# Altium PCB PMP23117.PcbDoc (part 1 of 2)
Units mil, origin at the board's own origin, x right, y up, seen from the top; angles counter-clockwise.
Board outline 3300 x 2800 mil, 6 copper layers (Top Layer, GND Layer 1, Signal Layer 1, GND Layer 2, Signal Layer3, Bottom Layer), stack 62.8 mil thick; 125 components, 38 nets, 250 pads, 683 vias.
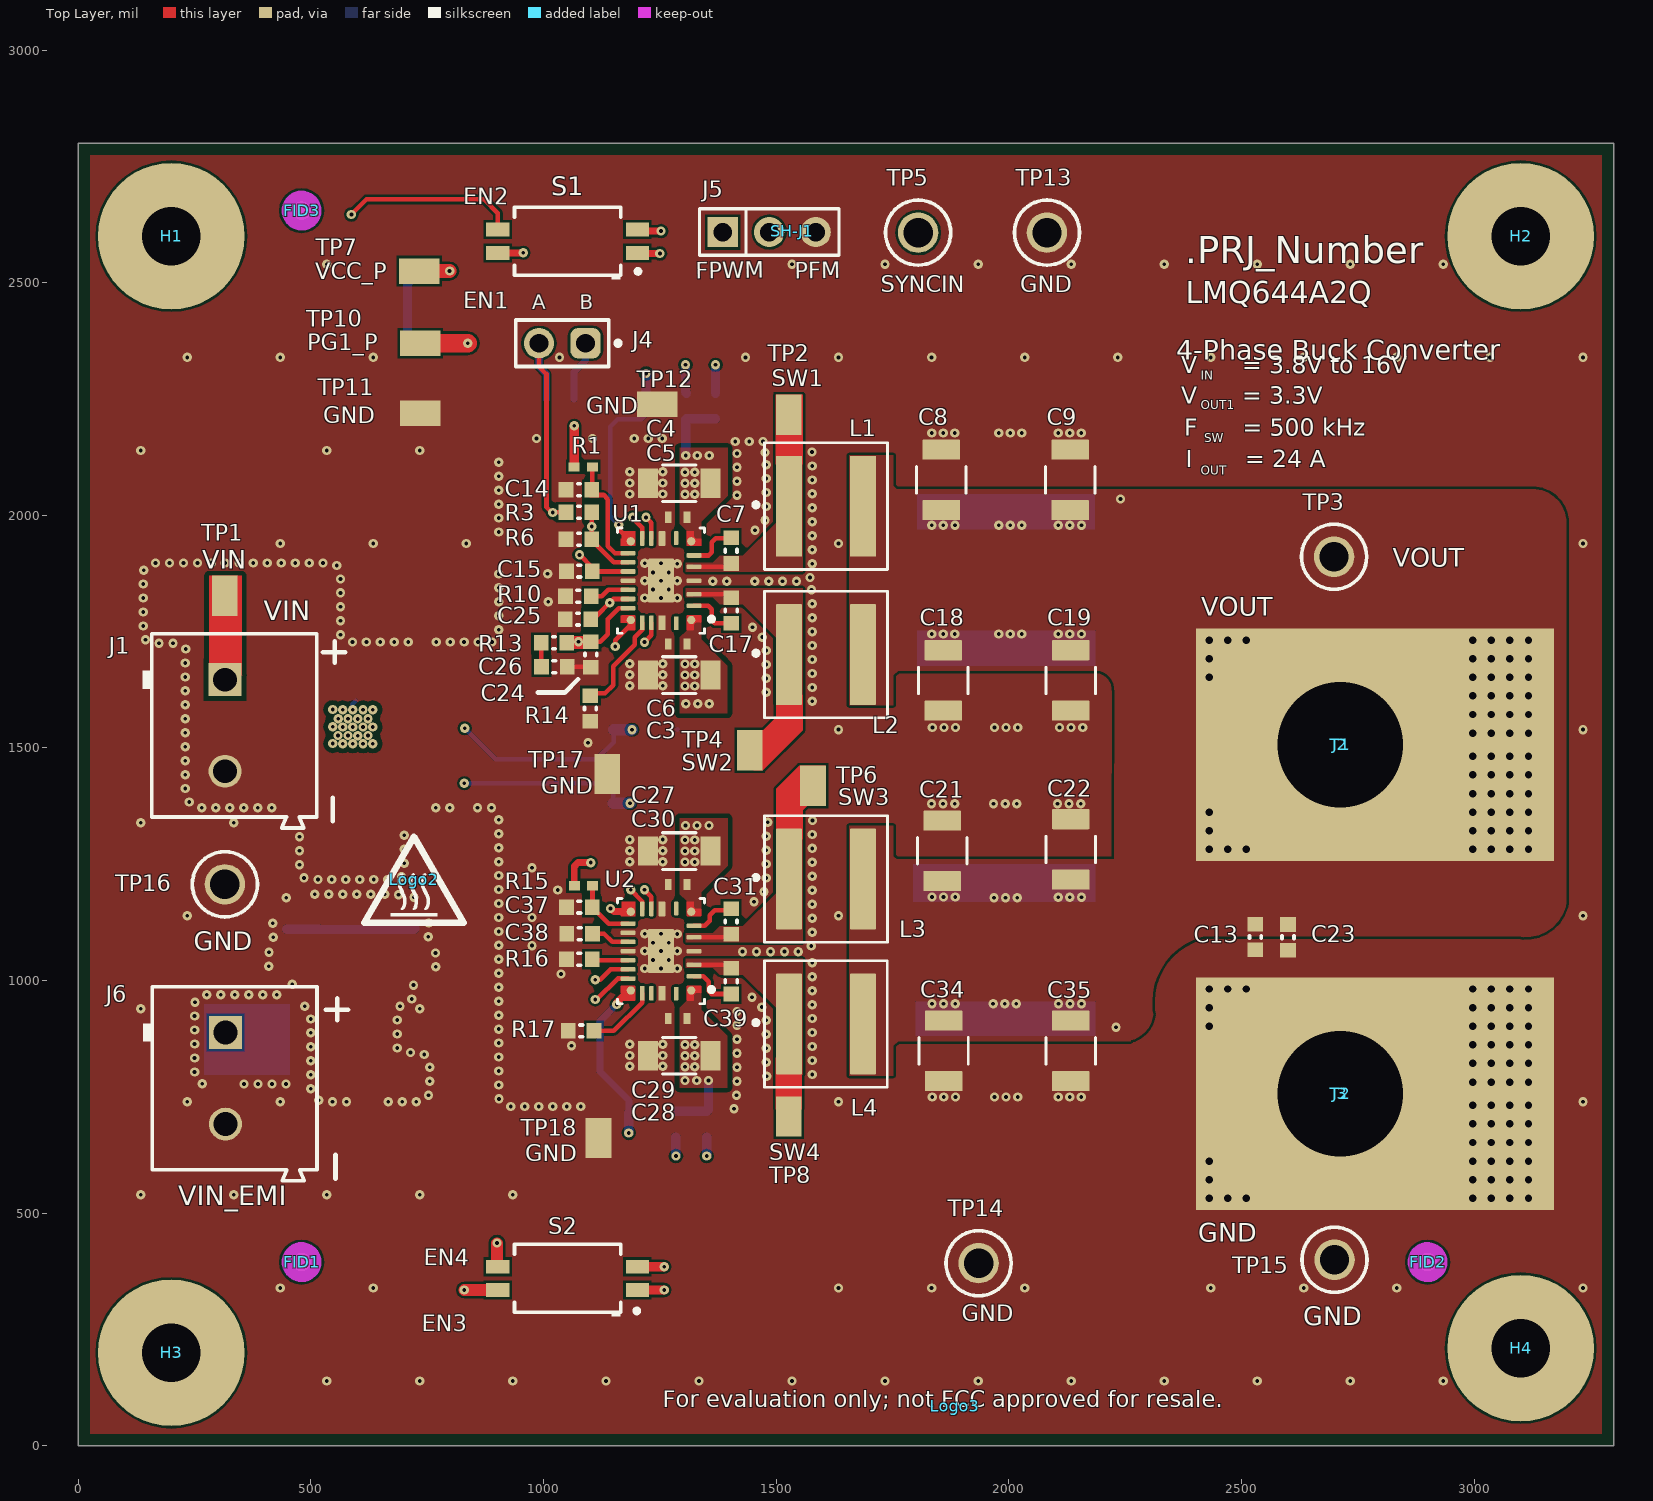
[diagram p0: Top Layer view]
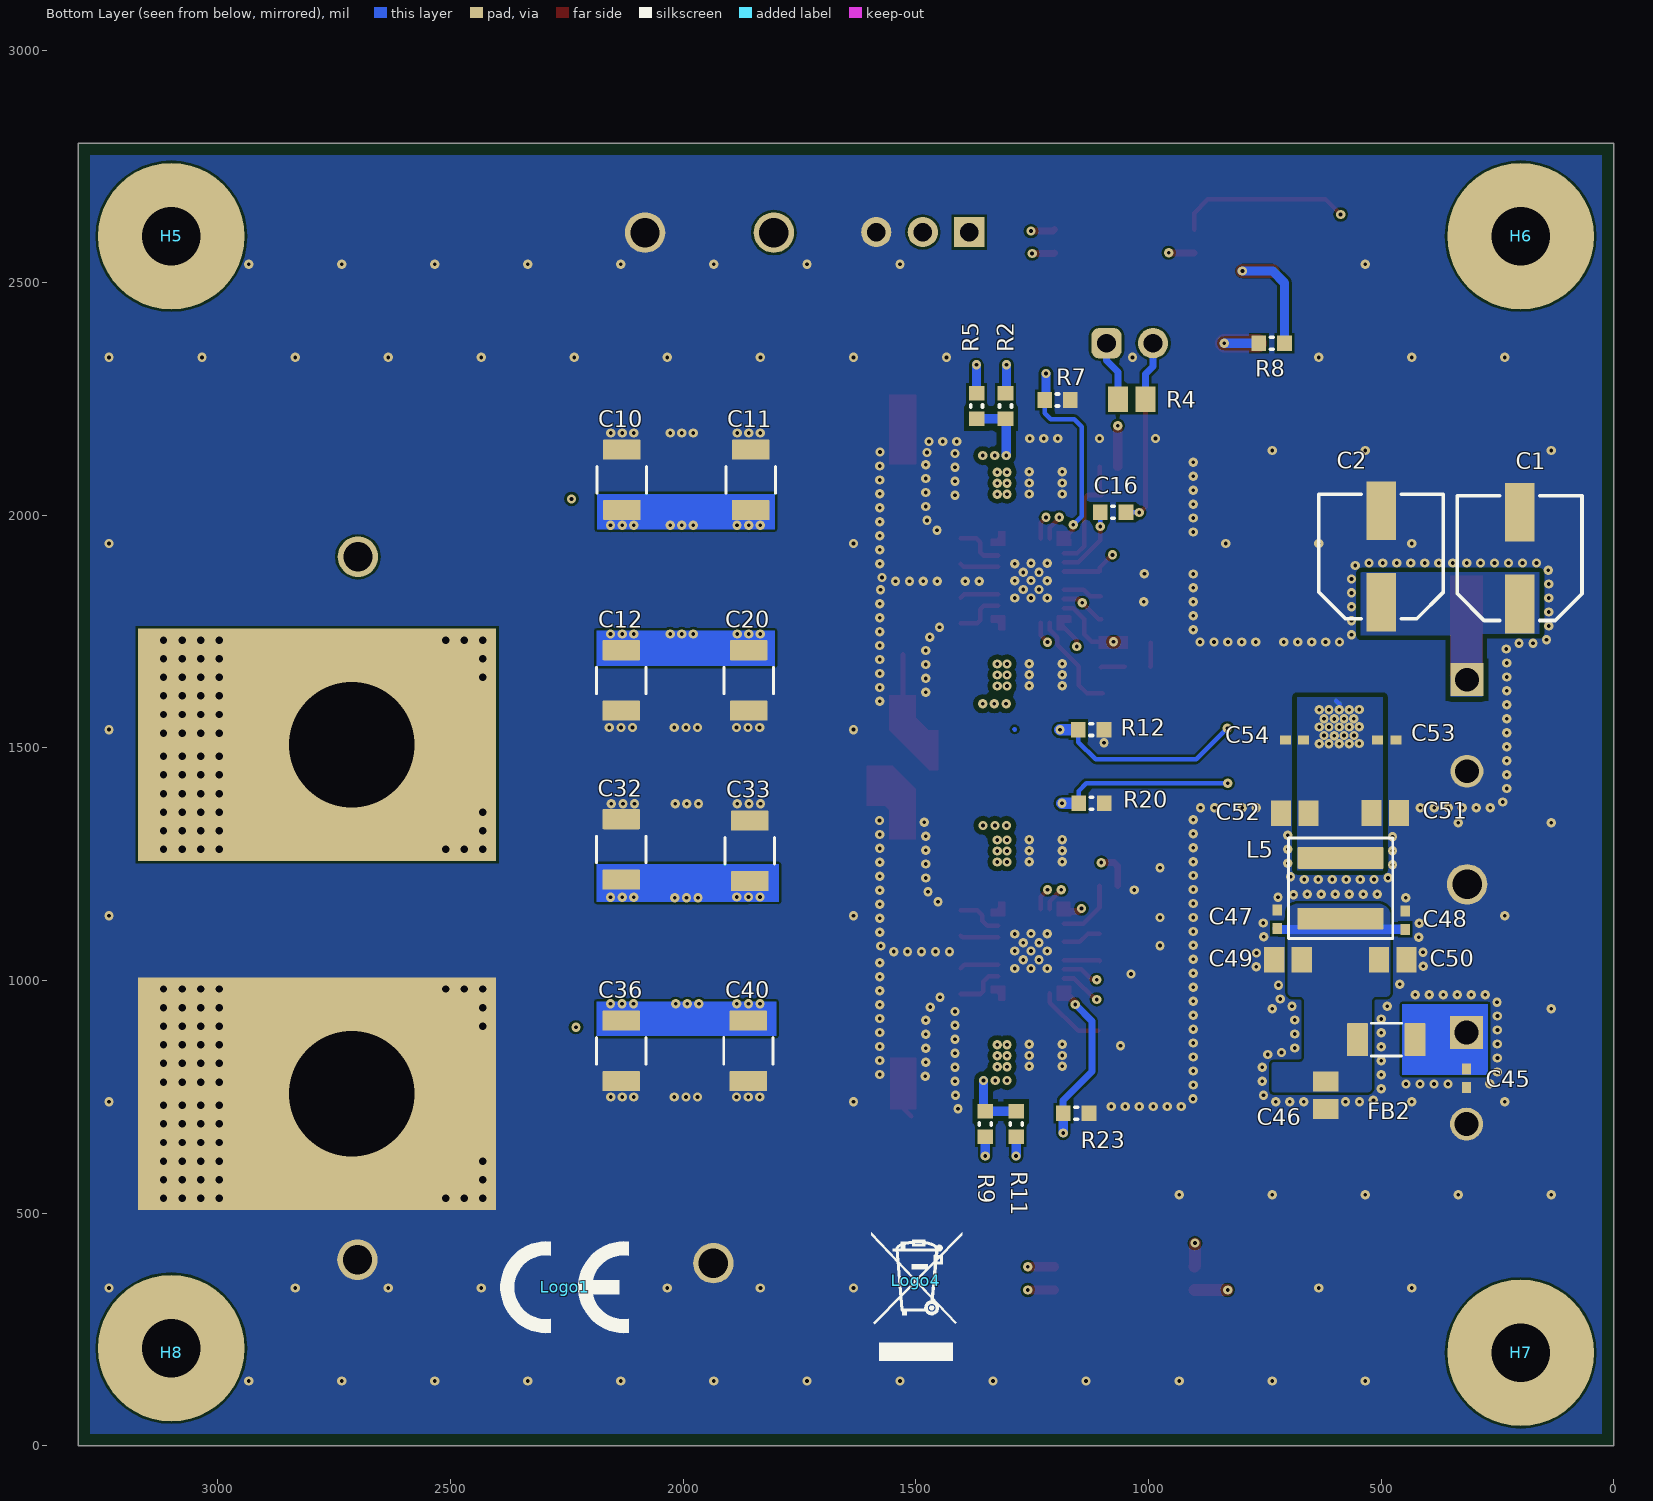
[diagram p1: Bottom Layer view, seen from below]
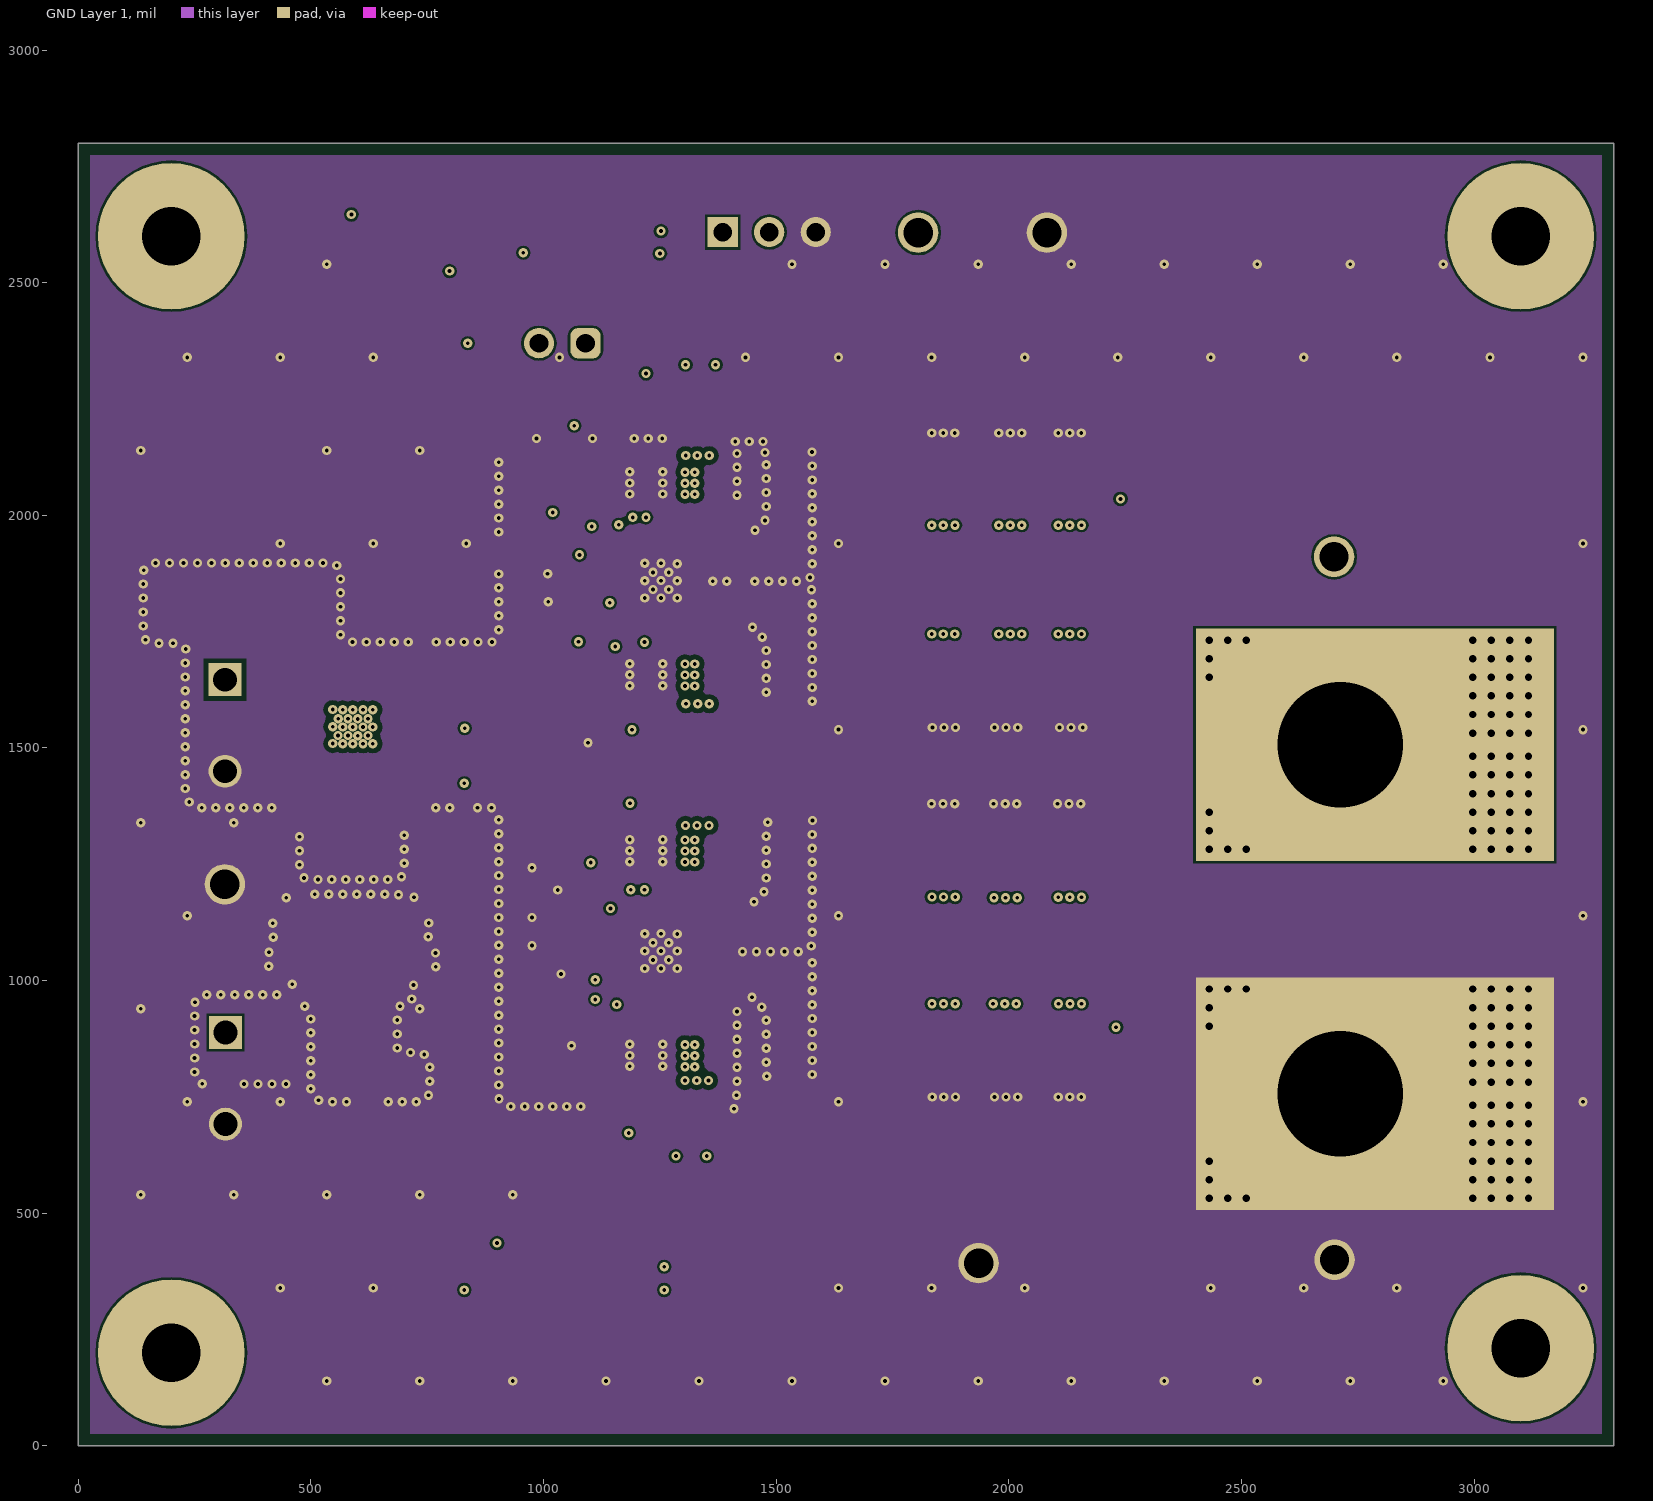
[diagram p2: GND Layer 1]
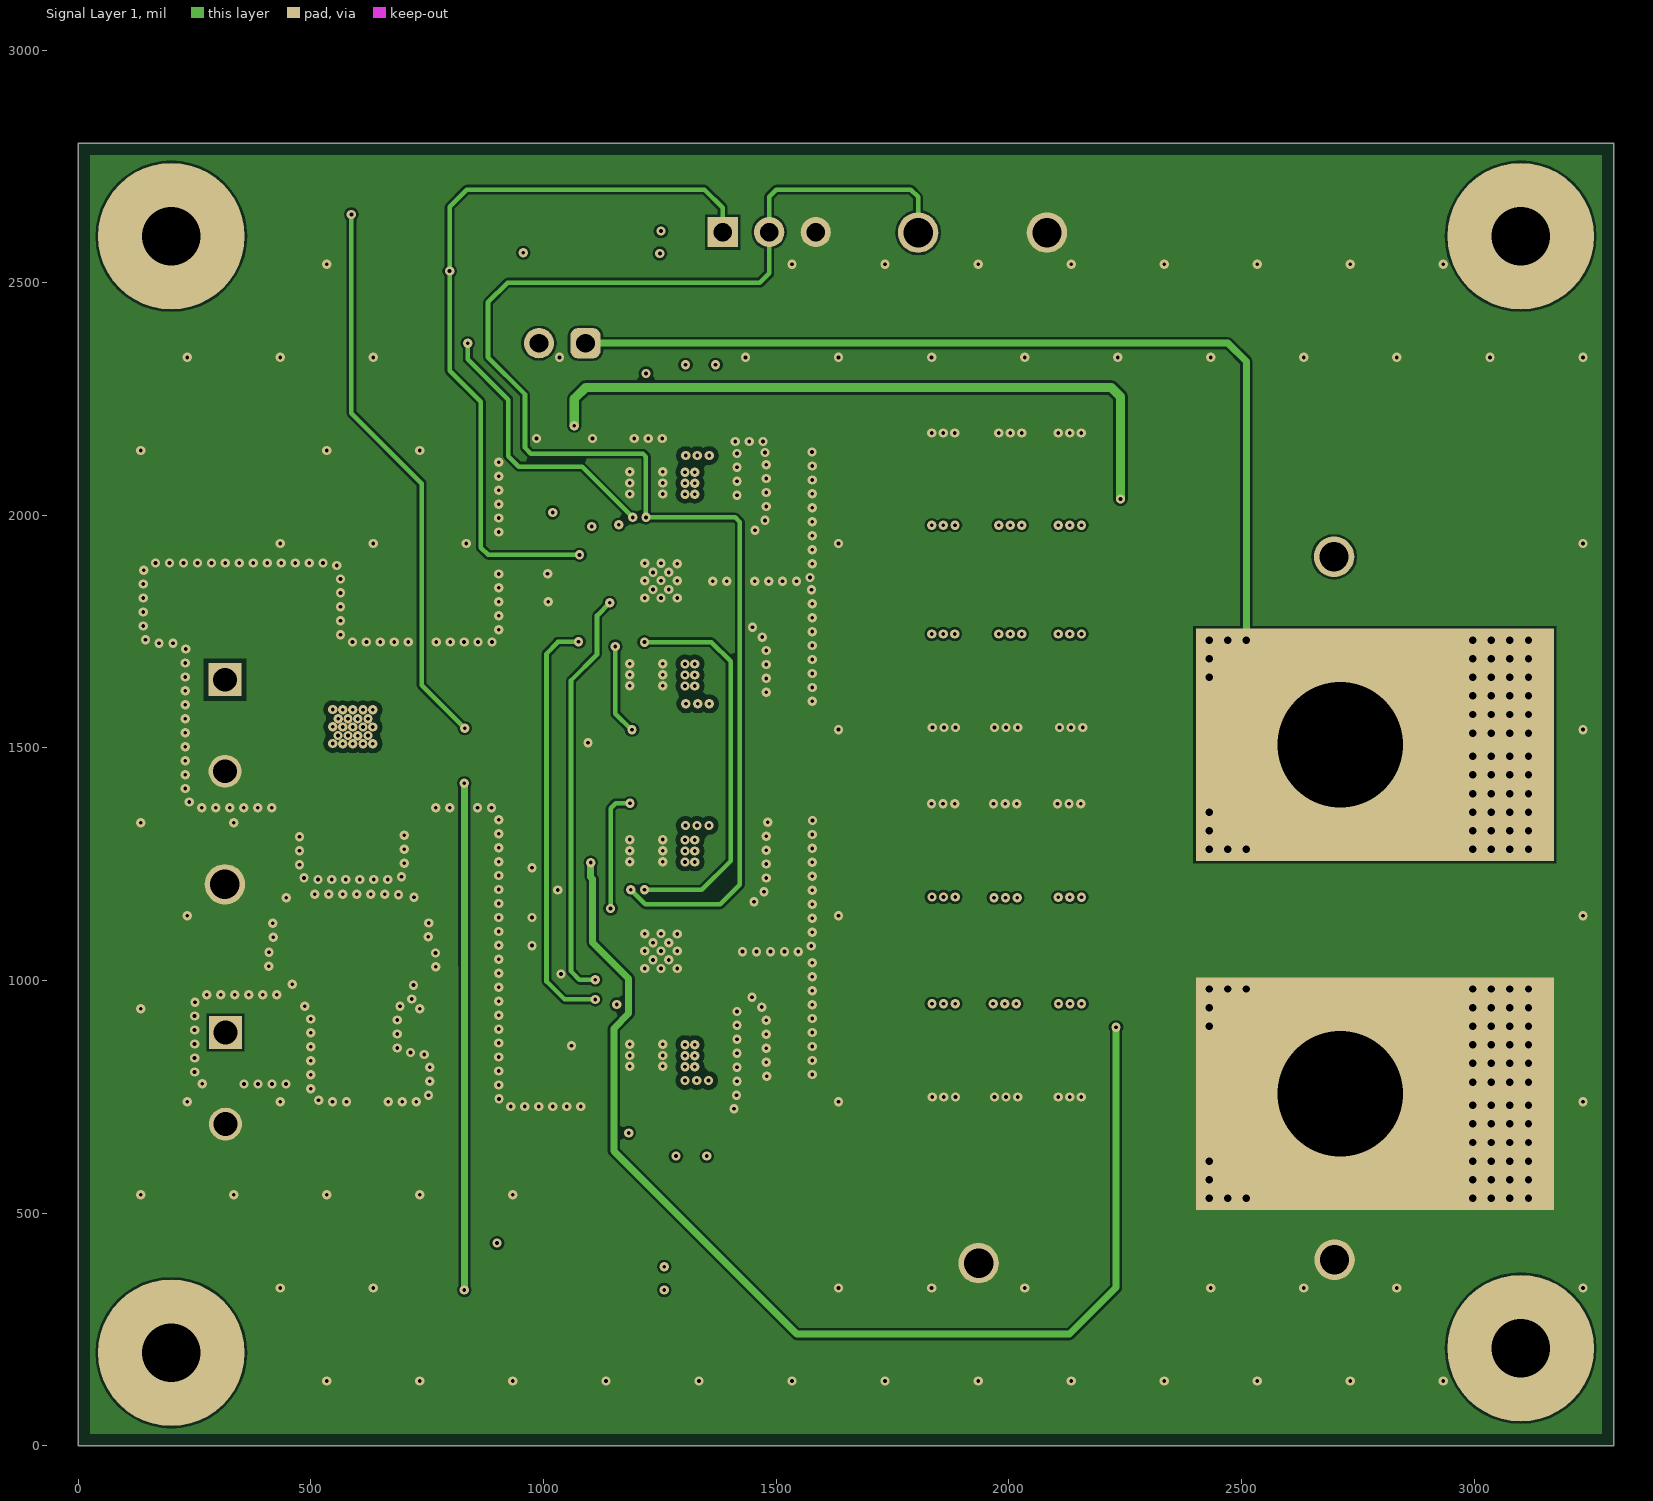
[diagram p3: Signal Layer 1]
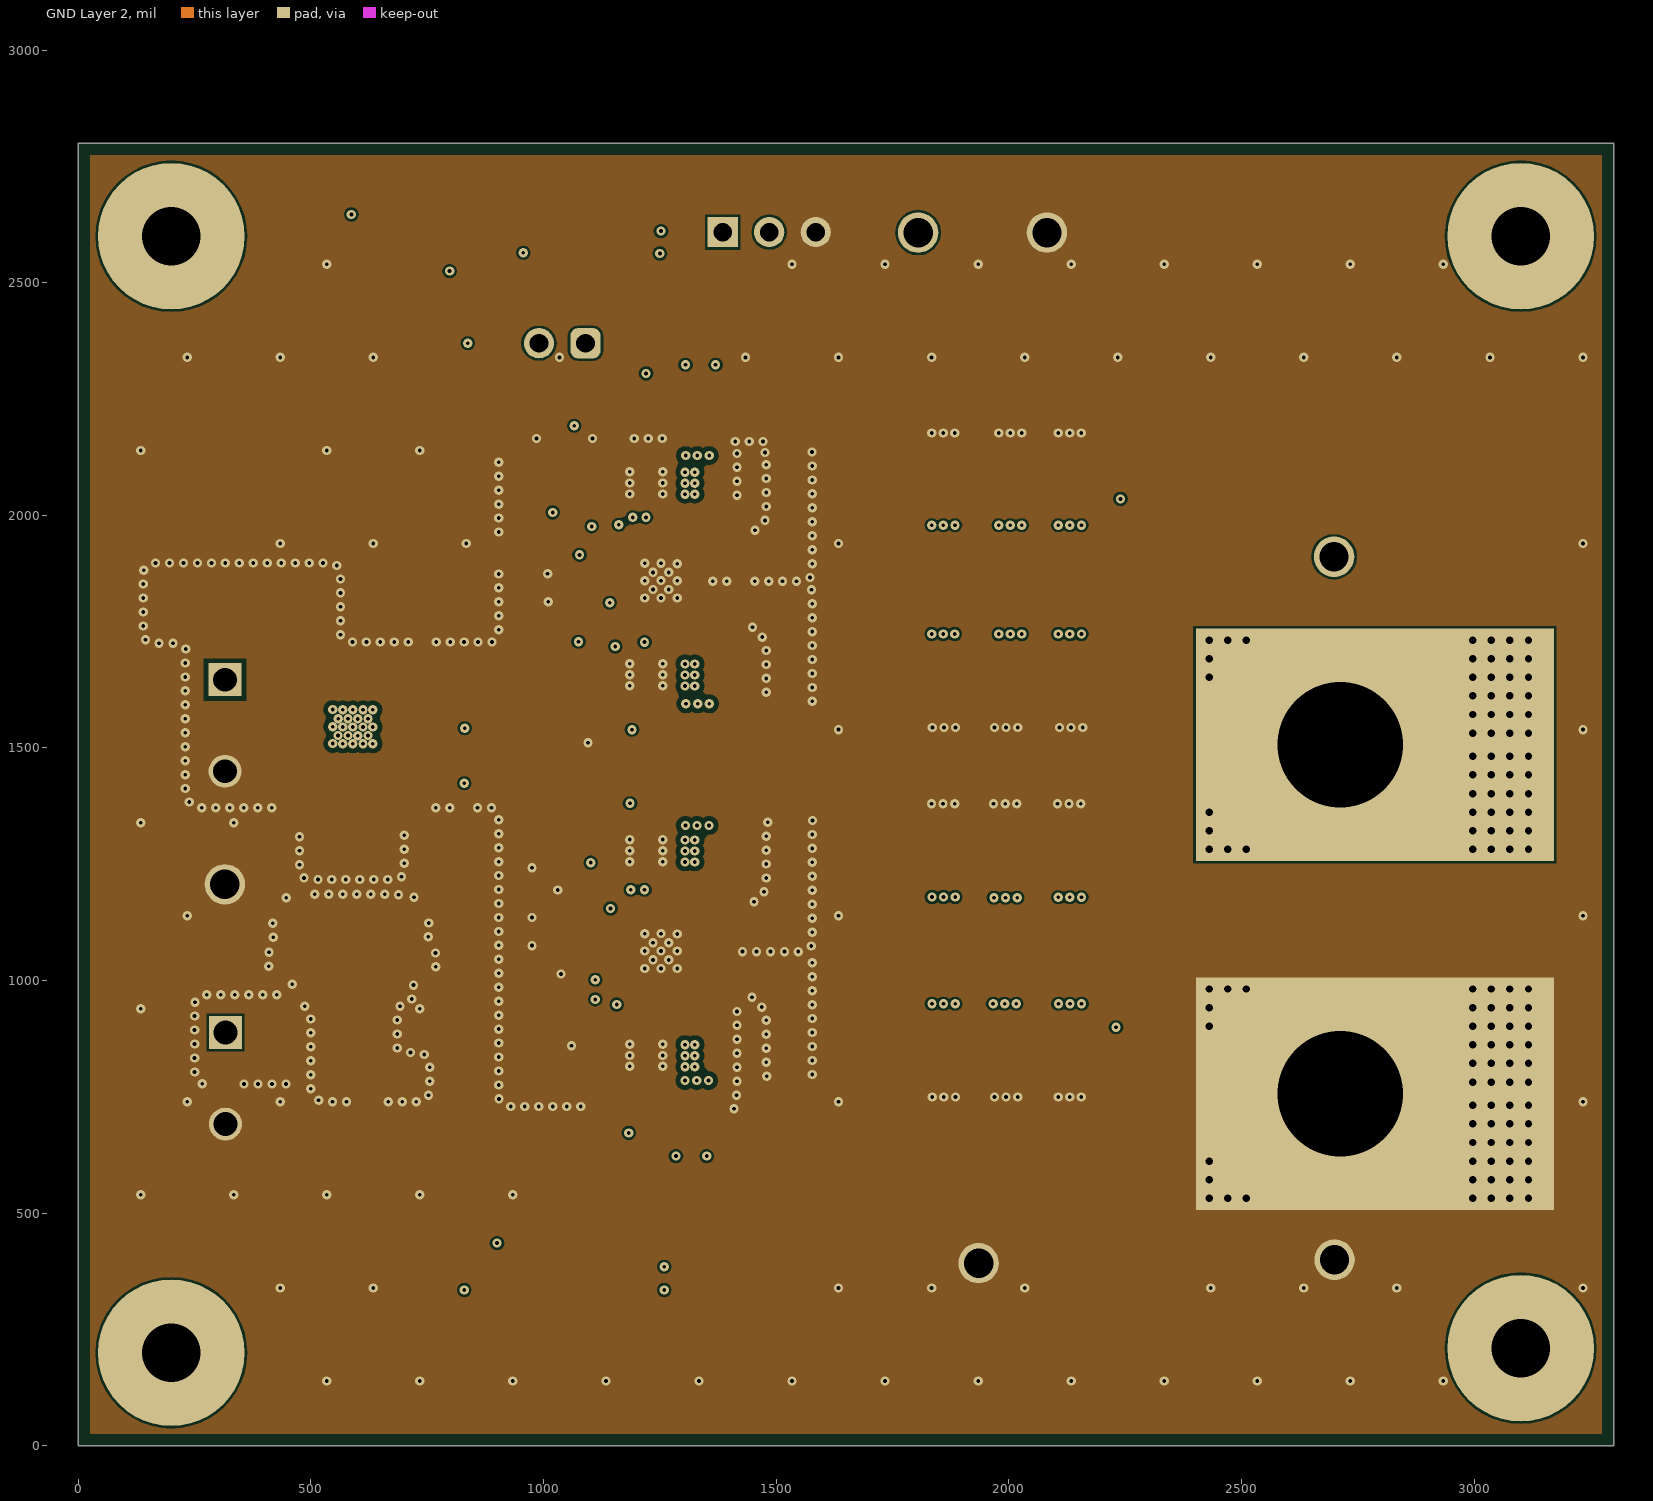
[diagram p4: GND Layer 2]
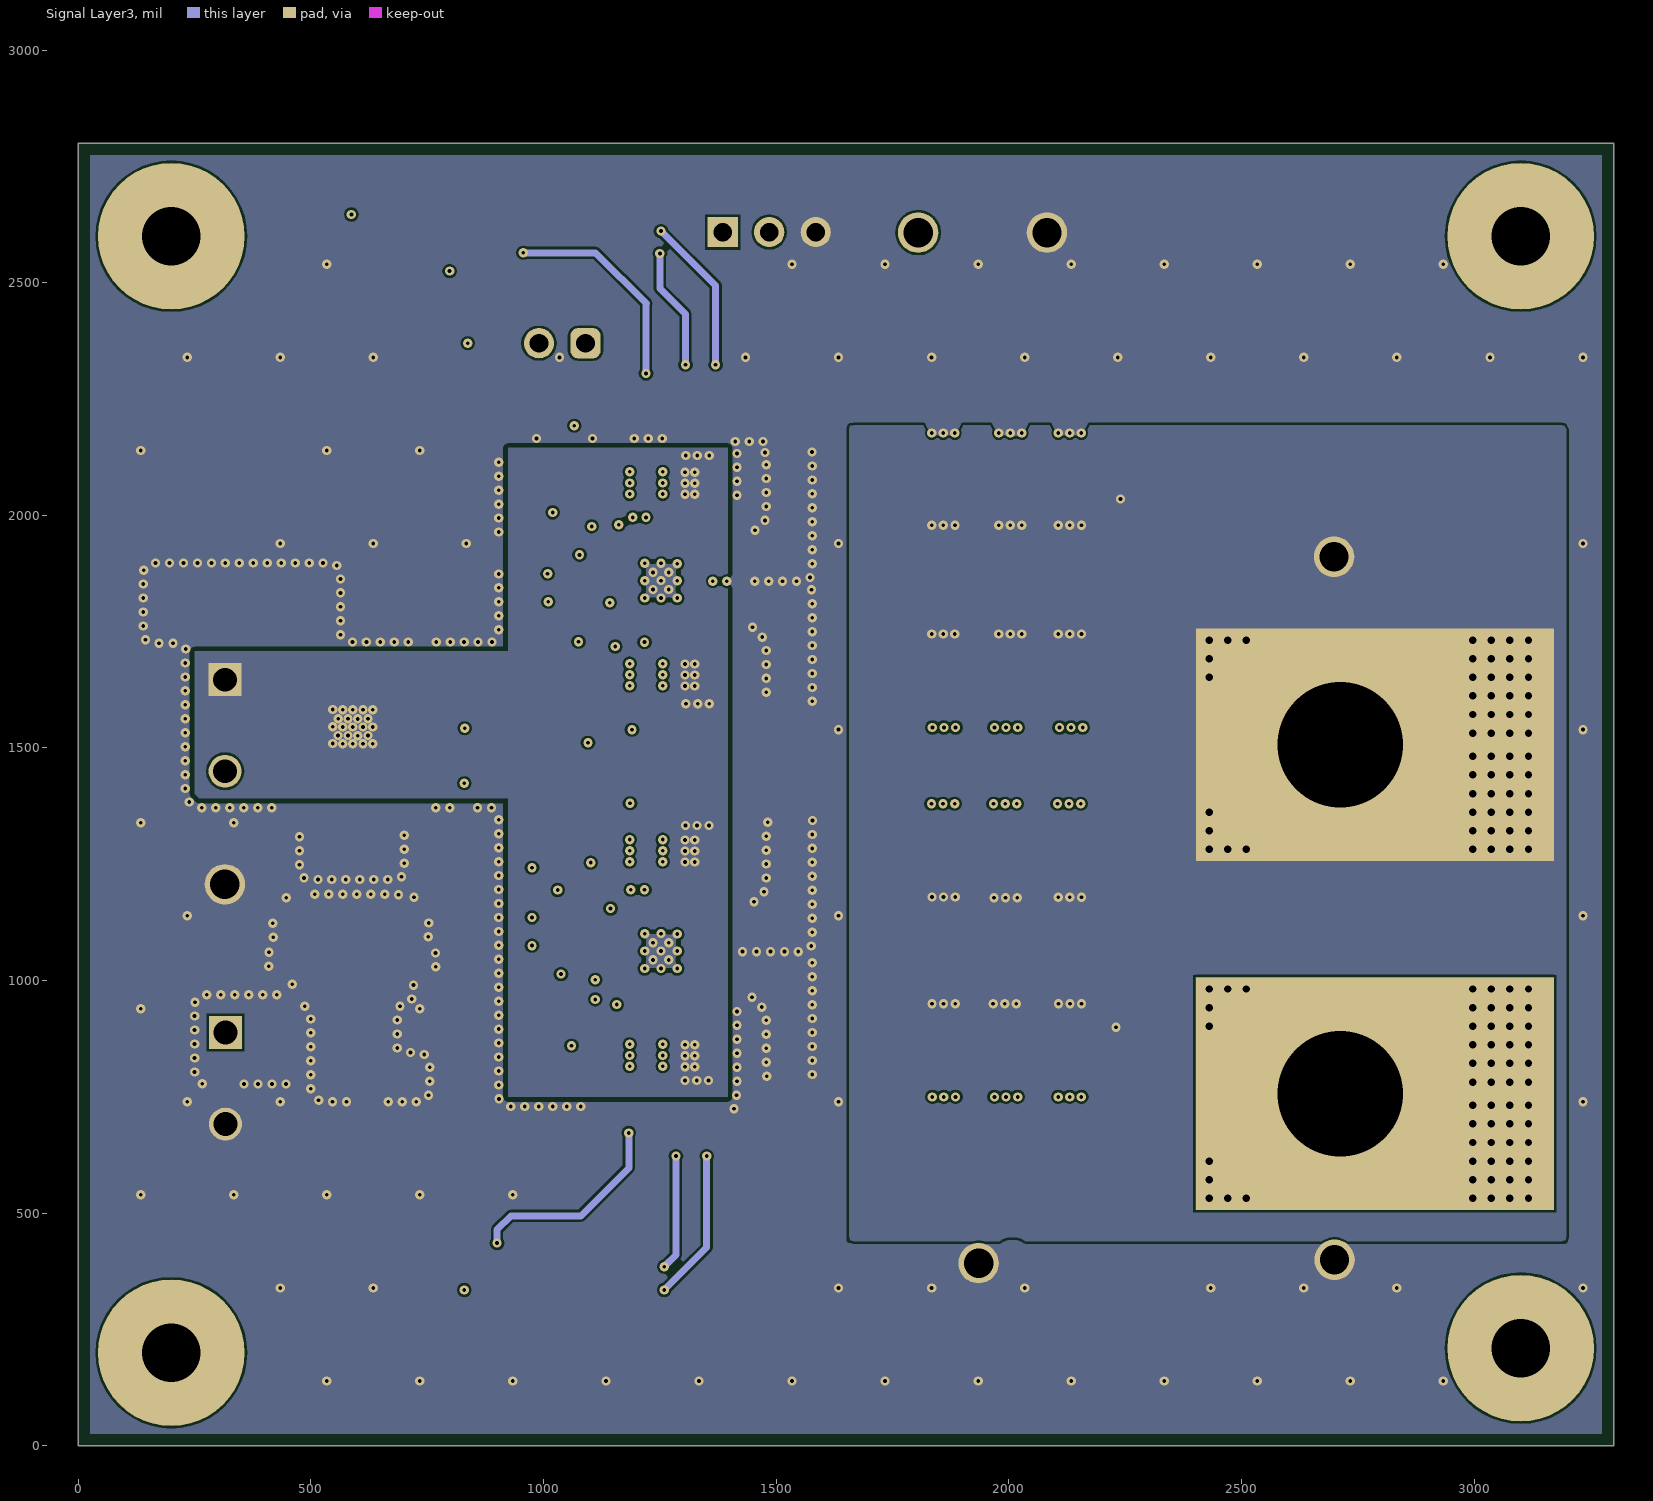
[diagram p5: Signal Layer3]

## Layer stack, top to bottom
Top Solder: solder mask 0.4, Solder Resist, Dk 3.5
Top Layer: signal copper 2.1
Dielectric 1: prepreg 8, FR-4 High Tg, Dk 4.2
GND Layer 1: signal copper 1.4
Dielectric 2: core 14.5, FR-4 High Tg, Dk 4.2
Signal Layer 1: signal copper 1.4
Dielectric 3: prepreg 8, FR-4 High Tg, Dk 4.2
GND Layer 2: signal copper 1.4
Dielectric4: core 14.5, FR-4 High Tg, Dk 4.2
Signal Layer3: signal copper 1.4
Dielectric6: prepreg 8, FR-4 High Tg, Dk 4.2
Bottom Layer: signal copper 2.1
Bottom Solder: solder mask 0.4, Solder Resist, Dk 3.5

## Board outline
0,0 0,2800 3300,2800 3300,0
cut-out: -339.5,-187

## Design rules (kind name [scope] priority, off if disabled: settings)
AcuteAngle [All] p1: minimum=4.50000000000000E+0001 checktracksonly=FALSE
AssemblyTestPointUsage [All] p1: valid=2
BoardOutlineClearance BoardOutlineClearance_MountingHoles [OnCopper and InComponentClass('Mounting Holes')] p1: gap=40 ignorepadtopadclearanceinfootprint=FALSE
BoardOutlineClearance BoardOutlineClearance_Poly [OnCopper and IsPoly] p2: gap=25 ignorepadtopadclearanceinfootprint=FALSE
BoardOutlineClearance [OnCopper and Not InComponentClass('Logo') and not InComponentClass('FiducialMark') and not InRegion(1000,500,4000,800) and not InPoly] p3: gap=30 ignorepadtopadclearanceinfootprint=FALSE
Clearance Clearance_Keepouts [((IsTrack Or IsArc) And Not InPoly) And IsFree and IsKeepOut vs ((IsTrack Or IsArc) And Not InPoly) And IsFree and IsKeepOut] p1: gap=0 ignorepadtopadclearanceinfootprint=FALSE
Clearance Clearance_Poly_VIN [InPolygon vs InNet('VIN')] p2: gap=10 ignorepadtopadclearanceinfootprint=FALSE
Clearance Clearance_Poly [InPolygon] p3: gap=5 ignorepadtopadclearanceinfootprint=FALSE
Clearance Clearance_FiducialMark [IsKeepOut and InComponentClass('FiducialMark') vs IsPad and InComponentClass('FiducialMark')] p4: gap=0 ignorepadtopadclearanceinfootprint=FALSE
Clearance [All] p5: gap=6 ignorepadtopadclearanceinfootprint=FALSE
ComponentClearance ComponentClearanceLugs2Banana [HasFootprint('Panduit_CXS70-14-C') vs HasFootprint('Johnson_108-0740-001')] p1: gap=0 collisioncheckmode=3 verticalgap=0 showdistances=FALSE
ComponentClearance ComponentClearanceJumperHeader [HasFootprint('PBC03SAAN') vs HasFootprint('SNT-100-BK-G')] p2: gap=0 collisioncheckmode=3 verticalgap=0 showdistances=FALSE
ComponentClearance ComponentClearance_MountingHoles_FiducialMarks [InComponentClass('Mounting Holes') vs InComponentClass('FiducialMark')] p3: gap=50 collisioncheckmode=3 verticalgap=10 showdistances=FALSE
ComponentClearance ComponentClearance_Shunt [InComponentClass('Header') vs InComponentClass('Shunt')] p4: gap=0 collisioncheckmode=3 verticalgap=0 showdistances=FALSE
ComponentClearance ComponentClearance_Logo [InComponentClass('Logo')] p5: gap=50 collisioncheckmode=3 verticalgap=10 showdistances=FALSE
ComponentClearance ComponentClearance_ScrewToNut [(HasFootprint('NY PMS 440 0025 PH')) vs (HasFootprint('Keystone_1902C'))] p6: gap=5 collisioncheckmode=3 verticalgap=10 showdistances=FALSE
ComponentClearance ComponentClearance_MountingHoles [InComponentClass('Mounting Holes')] p7: gap=175 collisioncheckmode=3 verticalgap=100000 showdistances=FALSE
ComponentClearance ComponentClearance_SmallPassives [HasFootprint('0201*') or HasFootprint('0402*') or HasFootprint('0508') or HasFootprint('0603*') or HasFootprint('0612') or HasFootprint('0805*') or HasFootprint('0815*') or HasFootprint('0830*') or HasFootprint('1206*') or HasFootprint('1210*') or HasFootprint('1808*') or HasFootprint('1812*') or HasFootprint('1825*') or HasFootprint('2010*') or HasFootprint('2220*') or HasFootprint('2225*') or HasFootprint('2512*') or HasFootprint('2728*') or HasFootprint('3518*') vs HasFootprint('0201*') or HasFootprint('0402*') or HasFootprint('0508') or HasFootprint('0603*') or HasFootprint('0612') or HasFootprint('0805*') or HasFootprint('0815*') or HasFootprint('0830*') or HasFootprint('1206*') or HasFootprint('1210*') or HasFootprint('1808*') or HasFootprint('1812*') or HasFootprint('1825*') or HasFootprint('2010*') or HasFootprint('2220*') or HasFootprint('2225*') or HasFootprint('2512*') or HasFootprint('2728*') or HasFootprint('3518*')] p8: gap=10 collisioncheckmode=3 verticalgap=10 showdistances=FALSE
ComponentClearance ComponentClearance_THtoSMT [IsThruComponent vs IsSMTComponent] p9: gap=40 collisioncheckmode=3 verticalgap=30 showdistances=FALSE
ComponentClearance ComponentClearance_THtoTH [IsThruComponent vs IsThruComponent] p10: gap=30 collisioncheckmode=3 verticalgap=30 showdistances=FALSE
ComponentClearance [All] p11: gap=10 collisioncheckmode=3 verticalgap=10 showdistances=FALSE
DiffPairsRouting [All] p1: maxlimit=100 minlimit=10 mostfreqgap=10 toplayer_minwidth=15 toplayer_maxwidth=15 toplayer_prefwidth=15 midlayer1_minwidth=15 midlayer1_maxwidth=15 midlayer1_prefwidth=15 midlayer2_minwidth=15 midlayer2_maxwidth=15 midlayer2_prefwidth=15 midlayer3_minwidth=15 midlayer3_maxwidth=15 midlayer3_prefwidth=15 midlayer4_minwidth=15 midlayer4_maxwidth=15 midlayer4_prefwidth=15 bottomlayer_minwidth=15 bottomlayer_maxwidth=15 bottomlayer_prefwidth=15 maxuncoupledlength=1000
FabricationTestPointUsage TestPointUsage [All] p1: valid=2 allowmultiple=FALSE
FabricationTestpoint Testpoint [All] p1: side=3 testpointundercomponent=TRUE minsize=40 maxsize=100 preferedsize=60 minholesize=0 maxholesize=40 preferedholesize=32 testpointgrid=1 allowsidetop=TRUE allowsidebottom=TRUE usegrid=TRUE gridtolerance=0.01
FanoutControl Fanout_LCC [IsLCC] p1: bgadir=Out bgaviamode=Centered fanoutstyle=Auto fanoutdirection=Alternating viagrid=1 // Fanout_LCC (Default Rule)
FanoutControl Fanout_BGA [IsBGA] p2: bgadir=Out bgaviamode=Centered fanoutstyle=Auto fanoutdirection=Alternating viagrid=1 // Fanout_BGA (Default Rule)
FanoutControl Fanout_Default [All] p4: bgadir=Out bgaviamode=Centered fanoutstyle=Auto fanoutdirection=Alternating viagrid=1 // Fanout_Default (Default Rule)
FanoutControl Fanout_Small [(CompPinCount < 5)] p5: bgadir=Out bgaviamode=Centered fanoutstyle=Auto fanoutdirection=OutThenIn viagrid=1 // Fanout_Small (Default Rule)
HoleSize [All] p1: absolutevalues=TRUE maxlimit=270 minlimit=6 maxpercent=80.000 minpercent=20.000
MinimumAnnularRing MinimumAnnularRing_ThermalPadVias [IsVia and InAnyComponent] p1: minimumring=5
MinimumAnnularRing [All] p2: minimumring=4
MinimumSolderMaskSliver MinimumSolderMaskSliver_Logo [InComponentClass('Logo') vs InComponentClass('Logo')] p1: minsoldermaskwidth=0.7
MinimumSolderMaskSliver [All] p2: minsoldermaskwidth=3.94
PlaneClearance [All] p1: clearance=8
PlaneConnect [All] p1: planeconnectstyle=Direct reliefexpansion=10 reliefentries=4 reliefconductorwidth=10 reliefairgap=10
PolygonConnect [All] p1: connectstyle=Direct reliefconductorwidth=10 reliefentries=4 polygonreliefangle="90 Angle" airgapwidth=10
RoutingVias ThermalPadVias [IsVia and InAnyComponent] p1: holewidth=8 width=16 viastyle="Through Hole" minholewidth=7.87 minwidth=10 maxholewidth=16 maxwidth=32
RoutingVias [All] p2: holewidth=8 width=16 viastyle="Through Hole" minholewidth=6 minwidth=15 maxholewidth=40 maxwidth=65
SilkToBoardRegionClearance [Not ((IsComment or IsDesignator) And (Hide <> 'False')) and not InRegion(1000,500,4000,800)] p1:
SilkToSilkClearance SilkToSilkClearance_Pb-FreeLogo [(HasFootprint('Pb-Free_Overlay_Medium') OR HasFootprint('Pb-Free_Overlay_Small')) vs (HasFootprint('Pb-Free_Overlay_Medium') OR HasFootprint('Pb-Free_Overlay_Small'))] p1: silktosilkclearance=0
SilkToSilkClearance [All] p2: silktosilkclearance=0
SilkToSolderMaskClearance SilkToComponentPadClearance [(IsPad or IsFill or IsRegion) and InAnycomponent] p1: minsilkscreentomaskgap=0 clearancetoexposedcopper=TRUE
SilkToSolderMaskClearance "Silk to Solder Mask Opening" [All] p2: minsilkscreentomaskgap=0 clearancetoexposedcopper=FALSE
SolderMaskExpansion [All] p1: expansion=1.97
Width [All] p1: maxlimit=100 minlimit=0.1 preferedwidth=10
14 further rules are at their usual default settings.

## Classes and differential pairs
component class Shunt: SH-J1
component class PMP23117_EMI_Filter: C45 C46 C47 C48 C49 C50 C51 C52 C53 C54 C55 FB2 J6 L5
component class PMP23117_Hardware: !PCB1 FID1 FID2 FID3 H1 H2 H3 H4 H5 H6 H7 H8 Logo1 Logo2 Logo3 Logo4 ZZ1 ZZ2 ZZ3 ZZ4 ZZ5
component class "Mounting Holes": H1 H2 H3 H4
component class FiducialMark: FID1 FID2 FID3
component class AssemblyNote: ZZ1 ZZ2 ZZ3 ZZ4 ZZ5
component class Header: J4 J5
component class PMP23117_Schematic: C1 C2 C3 C4 C5 C6 C7 C8 C9 C10 C11 C12 C13 C14 C15 C16 C17 C18 C19 C20 C21 C22 C23 C24 C25 C26 C27 C28 C29 C30 C31 C32 C33 C34 C35 C36 C37 C38 C39 C40 C? J1 J2 J3 J4 J5 L1 L2 L3 L4 mmm R1 R2 R3 R4 R5 R6 R7 R8 R9 R10 R11 R12 R13 R14 R15 R16 R17 R20 R23 S1 S2 SH-J1 T1 T2 TP1 TP2 TP3 TP4 TP5 TP6 TP7 TP8 TP10 TP11 TP12 TP13 TP14 TP15 TP16 TP17 TP18 U1 U2

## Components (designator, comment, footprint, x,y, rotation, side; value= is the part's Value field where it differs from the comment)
C1 "Cinblk" Panasonic_D 202,1908 r90 bottom value=47uF
C2 "Cinblk" Panasonic_D 499.81,1911.45 r90 bottom value=47uF
C3 "CIN1_P" 1206_190 1291.5,1656.76 r0 top value=10uF
C4 "CIN2_P" 1206_190 1291.5,2068.88 r0 top value=10uF
C5 "CHF2_P" 0402S 1287.95,1995.76 r180 top value=0.1uF
C6 "CHF1_P" 0402S 1287.95,1723.76 r180 top value=0.1uF
C7 "GCM188R71C104KA37J" 0603L 1403,1924 r270 top value=0.1uF
C8 "GRT32EC81A476KE13K" FP-GRT32EC81A476KE13K_1210-MFG 1854.91,2076.26 r270 top value=47µF
C9 "GRT32EC81A476KE13K" FP-GRT32EC81A476KE13K_1210-MFG 2131.8,2076.26 r270 top value=47µF
C10 "GRT32EC81A476KE13K" FP-GRT32EC81A476KE13K_1210-MFG 2131.8,2076.26 r270 bottom value=47µF
C11 "GRT32EC81A476KE13K" FP-GRT32EC81A476KE13K_1210-MFG 1854.91,2076.26 r270 bottom value=47µF
C12 "GRT32EC81A476KE13K" FP-GRT32EC81A476KE13K_1210-MFG 2132.96,1645.19 r90 bottom value=47µF
C13 "Co11" 0603L 2530,1093.55 r270 top value=1uF
C14 "CBIAS_P" 0603L 1075.89,2055 r0 top value=0.1uF
C15 "CVCC_P" 0603L 1076.8,1880.26 r0 top value=1uF
C16 "CFF" 0603L 1075.89,2006.42 r0 bottom value=22pF
C17 "GCM188R71C104KA37J" 0603L 1403.18,1795.65 r270 top value=0.1uF
C18 "GRT32EC81A476KE13K" FP-GRT32EC81A476KE13K_1210-MFG 1859.1,1645.2 r90 top value=47µF
C19 "GRT32EC81A476KE13K" FP-GRT32EC81A476KE13K_1210-MFG 2132.96,1645.2 r90 top value=47µF
C20 "GRT32EC81A476KE13K" FP-GRT32EC81A476KE13K_1210-MFG 1859.1,1645.2 r90 bottom value=47µF
C21 "GRT32EC81A476KE13K" FP-GRT32EC81A476KE13K_1210-MFG 1856.8,1278.98 r270 top value=47µF
C22 "GRT32EC81A476KE13K" FP-GRT32EC81A476KE13K_1210-MFG 2132.96,1282 r270 top value=47µF
C23 "Co12" 0603L 2600,1093.01 r270 top value=1uF
C24 "CHFP" 0603L 1101.8,1700.76 r90 top value=10pF
C25 "GCM188R71C104KA37J" 0603L 1073.96,1776.95 r0 top value=0.1uF
C26 "GCM188R71H472KA37D" 0603L 1023.05,1674.35 r0 top value=4700pF
C27 "CIN1_S" 1206_190 1291.5,1278.48 r0 top value=10uF
C28 "CIN2_S" 1206_190 1291.5,838.48 r0 top value=10uF
C29 "CHF2_S" 0402S 1287.95,918.48 r180 top value=0.1uF
C30 "CHF1_S" 0402S 1287.95,1206.86 r180 top value=0.1uF
C31 "GCM188R71C104KA37J" 0603L 1403,1127 r90 top value=0.1uF
C32 "GRT32EC81A476KE13K" FP-GRT32EC81A476KE13K_1210-MFG 2132.96,1282 r270 bottom value=47µF
C33 "GRT32EC81A476KE13K" FP-GRT32EC81A476KE13K_1210-MFG 1856.8,1278.98 r270 bottom value=47µF
C34 "GRT32EC81A476KE13K" FP-GRT32EC81A476KE13K_1210-MFG 1859.86,848.92 r90 top value=47µF
C35 "GRT32EC81A476KE13K" FP-GRT32EC81A476KE13K_1210-MFG 2132.96,849 r90 top value=47µF
C36 "GRT32EC81A476KE13K" FP-GRT32EC81A476KE13K_1210-MFG 2132.96,849 r90 bottom value=47µF
C37 "CBIAS_S" 0603L 1076.76,1157.97 r0 top value=0.1uF
C38 "CVCC_S" 0603L 1077.59,1100.88 r0 top value=1uF
C39 "GCM188R71C104KA37J" 0603L 1403.18,998.88 r90 top value=0.1uF
C40 "GRT32EC81A476KE13K" FP-GRT32EC81A476KE13K_1210-MFG 1859.86,848.92 r90 bottom value=47µF
C45 "CFLTIN" 0402L 316.22,790 r270 bottom value=0.1uF
C46 "CFLT7" 0805L 619.16,753.76 r270 bottom value=2.2uF
C47 "CFLT6" 0402L 723,1132 r90 bottom value=0.022uF
C48 "CFLT5" 0402L 448,1130 r90 bottom value=0.022uF
C49 "CFLT4" 0805L 700,1045 r0 bottom value=2.2uF
C50 "CFLT3" 0805L 475,1045 r180 bottom value=2.2uF
C51 "CFLT2" 0805L 490.8,1360.36 r180 bottom value=2.2uF
C52 "CFLT1" 0805L 685.8,1360 r0 bottom value=2.2uF
C53 "CFLTHF2" 0402L 488,1517 r180 bottom value=0.1uF
C54 "CFLTHF1" 0402L 686,1517 r0 bottom value=0.1uF
FB2 "BLM31SN500SH1L" FP-BLM31SN500SH1L_1206-MFG 488.59,873.15 r0 bottom
FID1 "Fiducial" Fiducial10-20 480,395 r0 top
FID2 "Fiducial" Fiducial10-20 2900,395 r0 top
FID3 "Fiducial" Fiducial10-20 480,2655 r0 top
H1 "NY PMS 440 0025 PH" "NY PMS 440 0025 PH"#1 200,2600 r0 top
H2 "NY PMS 440 0025 PH" "NY PMS 440 0025 PH"#1 3100,2600 r0 top
H3 "NY PMS 440 0025 PH" "NY PMS 440 0025 PH"#1 200,200 r0 top
H4 "NY PMS 440 0025 PH" "NY PMS 440 0025 PH"#2 3100,200 r0 top
H5 "1902C" Keystone_1902C 3100,2600 r180 bottom
H6 "1902C" Keystone_1902C 200,2600 r180 bottom
H7 "1902C" Keystone_1902C 200,200 r180 bottom
H8 "1902C" Keystone_1902C 3100,200 r180 bottom
J1 "VIN" Wurth_691101710002 315.37,1548.43 r270 top
J2 "+VOUT" Johnson_108-0740-001 2712,1507 r0 top
J3 "GND" Johnson_108-0740-001 2712,757 r0 top
J4 "BODE" TSW-102-07-G-S 1040.05,2370 r180 top
J5 "MODE" PBC03SAAN 1484.95,2608.88 r0 top
J6 "VIN_EMI" Wurth_691101710002 316.22,790 r270 top
L1 "XGL6060-332MEC" FP-XGL6060-332MEC_SMT_6MM51_6MM71-MFG 1606.92,2019.76 r0 top value=3.3uH
L2 "XGL6060-332MEC" FP-XGL6060-332MEC_SMT_6MM51_6MM71-MFG 1606.92,1700.76 r0 top value=3.3uH
L3 "XGL6060-332MEC" FP-XGL6060-332MEC_SMT_6MM51_6MM71-MFG 1606.92,1218.48 r0 top value=3.3uH
L4 "XGL6060-332MEC" FP-XGL6060-332MEC_SMT_6MM51_6MM71-MFG 1606.8,906.67 r0 top value=3.3uH
L5 "LFLT" FP-XEL5030-102MEB_SMT_5MM28_5MM48-MFG 586.9,1198.43 r90 bottom
Logo1 "CE Mark" CE_Mark_5mm 2255,340.85 r180 bottom
Logo2 "CAUTION HOT SURFACE" IEC_HotSurface_Small 721.43,1217.04 r0 top (schematic designator LOGO2)
Logo3 "FCC disclaimer" FCC_disclaimer 1883.51,85 r0 top
Logo4 "WEEE logo" WEEE_Minimum 1499.8,355 r180 bottom
R1 "RSNS1_P" 0402L 1085,2104.26 r180 top value=0
R2 "CRCW0603200KFKEA" 0603L 1307.1,2235.11 r90 bottom value=200k
R3 "RFBT" 0603L 1075.89,2006.42 r0 top value=100k
R4 "RINJ" 0805L 1035.84,2249.81 r0 bottom value=49.9
R5 "CRCW0603200KFKEA" 0603L 1369.32,2235.11 r90 bottom value=200k
R6 "RFBB" 0603L 1075.89,1948.41 r0 top value=32.0k
R7 "CRCW0603100KFKEA" 0603L 1195.34,2247.9 r0 bottom value=100k
R8 "RPG1_P" 0603L 735,2370 r0 bottom value=100k
R9 "CRCW0603200KFKEA" 0603L 1350.73,691.57 r270 bottom value=200k
R10 "CRCW060331K6FKEA" 0603L 1074.79,1825.93 r0 top value=31.6k
R11 "CRCW0603200KFKEA" 0603L 1284.29,691.57 r270 bottom value=200k
R12 "CRCW0603100KFKEA" 0603L 1123.06,1539.5 r0 bottom value=100k
R13 "CRCW06036K49FKEA" 0603L 1022.32,1726.13 r0 top value=6.49k
R14 "CRCW060373K2FKEA" 0603L 1100.66,1585 r90 top value=73.2k
R15 "RSNS1_S" 0402L 1085.61,1203.88 r0 top value=0
R16 "CRCW060331K6FKEA" 0603L 1076.76,1046.12 r0 top value=31.6k
R17 "CRCW060341K2FKEA" 0603L 1080.81,891.85 r0 top value=41.2k
R20 "CRCW0603100KFKEA" 0603L 1122.51,1381 r0 bottom value=100k
R23 "CRCW0603100KFKEA" 0603L 1155.13,715 r0 bottom value=100k
S1 "218-2LPST" SW_218-2LP 1051.68,2589.19 r180 top
S2 "218-2LPST" SW_218-2LP 1051.68,360 r180 top
SH-J1 "SNT-100-BK-G" SNT-100-BK-G 1535,2610.81 r180 top value=1x2
T1 "VOUT" Panduit_CXS70-14-C 2712,1507 r180 top
T2 "GND" Panduit_CXS70-14-C 2712,757 r180 top
TP1 "VIN" Harwin_S2751-46R 315,1827 r90 top
TP2 "SW1" Harwin_S2751-46R 1527,2216 r270 top
TP3 "VOUT" Keystone5010 2699,1911 r90 top
TP4 "SW2" Harwin_S2751-46R 1443,1495 r270 top
TP5 "SYNCIN" Keystone5013 1805,2607.75 r270 top
TP6 "SW3" Harwin_S2751-46R 1579,1419 r270 top
TP7 "VCC_P" Harwin_S2751-46R 733.04,2525 r180 top
TP8 "SW4" Harwin_S2751-46R 1527,708 r90 top
TP10 "PG1_P" Harwin_S2751-46R 735,2370 r180 top
TP11 "GND" Harwin_S2751-46R 735,2219.81 r0 top
TP12 "GND" Harwin_S2751-46R 1244.35,2238.91 r180 top
TP13 "GND" Keystone5011 2081.99,2607.75 r90 top
TP14 "GND" Keystone5011 1935,392.64 r270 top
TP15 "GND" Keystone5011 2700,400 r90 top
TP16 "GND" Keystone5011 315,1206.93 r90 top
TP17 "GND" Harwin_S2751-46R 1137,1444 r270 top
TP18 "GND" Harwin_S2751-46R 1118.04,661.75 r270 top
U1 "LMQ644A2QRXARQ1" RXA0024A-MFG 1252.43,1859.63 r180 top
U2 "LMQ644A2QRXARQ1" RXA0024A-MFG 1252.43,1063.48 r180 top
ZZ1 "This Assembly Note is for PCB labels only" AssemblyNoteLabel -280,3450 r0 top
ZZ2 "These assemblies are ESD sensitive, ESD precautions shall be observed." AssemblyNote -280,3320 r0 top
ZZ3 "These assemblies must be clean and free from flux and all contaminants. Use of no clean flux is not acceptable." AssemblyNote -280,3190 r0 top
ZZ4 "These assemblies must comply with workmanship standards IPC-A-610 Class 2, unless otherwise specified." AssemblyNote -280,3060 r0 top
ZZ5 "SH-J1 should be placed between pin 2 and 3 of J5" AssemblyNote -280,2925 r0 top

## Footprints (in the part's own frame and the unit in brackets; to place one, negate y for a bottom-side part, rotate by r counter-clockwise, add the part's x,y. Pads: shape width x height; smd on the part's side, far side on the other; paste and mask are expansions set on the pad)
0402L [mm] "0402 from SM-752 data"
  rect 0.6x0.5 smd: 1(-0.5,0) 2(0.5,0)
  body extent -0.55,-0.3 0.55,0.3, height 0.6
0402S [mil] "Based on C0402S footprint from PADS legacy"
  rect 15x24 smd: 1(-20,0) 2(20,0)
  body extent -22,-12 22,12, height 24
0603L [mm] "0603 from SM-752 data"
  rect 0.8x0.85 smd: 1(-0.7,0) 2(0.7,0)
  silkscreen extent -0.07,-0.33 0.07,0.33, body extent -0.87,-0.47 0.87,0.47, height 1
0805L [mm] "0805 from SM-752 data"
  rect 1.1x1.4 smd: 1(-0.75,0) 2(0.75,0)
  body extent -1.1,-0.72 1.1,0.72, height 1.45
1206_190 [mm] "1206_190"
  rect 1.1x1.6 smd: 1(-1.7,0) 2(1.7,0)
  silkscreen extent -0.9,-1 0.9,1, body extent -1.75,-0.95 1.75,0.95, height 1.9
AssemblyNote [mil] "Assembly Note"
AssemblyNoteLabel [mil] "Assembly Note for PCB Labels"
CE_Mark_5mm [mil] "Minimum text height for CE Mark"
  silkscreen extent -138,-98 138,98
FCC_disclaimer [mil]
Fiducial10-20 [mm]
  round 1 smd mask+0.5: 1(0,0)
  Top Layer keep-out circle w1.178: c0,0 r0.5
FP-BLM31SN500SH1L_1206-MFG [mm]
  rrect9% 1.15x1.8 smd paste+0 mask+0: 1(-1.575,0) 2(1.575,0)
  silkscreen extent -0.82,-0.9 0.82,0.9, body extent -1.6,-0.8 1.6,0.8, height 1.3
FP-GRT32EC81A476KE13K_1210-MFG [mm]
  rrect9% 1.1x2.05 smd paste+0 mask+0: 1(-1.65,0) 2(1.65,0)
  silkscreen extent -0.72,-1.35 0.72,1.35, body extent -2.3,-1.45 2.3,1.45, height 0.25
FP-XEL5030-102MEB_SMT_5MM28_5MM48-MFG [mm]
  rrect8% 1.18x4.7 smd paste+0 mask+0: 1(-1.655,0) 2(1.655,0)
  silkscreen extent -2.74,-2.84 2.74,2.84, body extent -2.64,-2.74 2.64,2.74, height 3.1
FP-XGL6060-332MEC_SMT_6MM51_6MM71-MFG [mm]
  rrect7% 1.43x5.5 smd paste+0 mask+0: 1(-2.02,0) 2(2.02,0)
  silkscreen extent -3.95,-3.45 3.35,3.45, body extent -3.45,-3.55 3.45,3.55, height 0.25
Harwin_S2751-46R [mm] "Test Point, SMT"
  rect 2.2x1.4 smd: 1(0,0)
  body extent -1,-0.6 1,0.6, height 1.4
IEC_HotSurface_Small [mil]
  silkscreen extent -107,-93 107,92
Johnson_108-0740-001 [mm] "Banana Jack Uninsulated Standard Type"
  round 12 hole 6.858: 1(0,0)
  body extent -4.77,-5.43 4.75,5.57, height 2.39
Keystone5010 [mil] "Keystone Multipurpose loops"
  round 87 hole 63: 1(0,0)
  silkscreen extent -70,-70 70,70, body extent -63,-63 63,62, height 319
Keystone5011 [mil] "Keystone Multipurpose loops"
  round 87 hole 63: 1(0,0)
  silkscreen extent -70,-70 70,70, body extent -63,-63 63,62, height 319
Keystone5013 [mil] "Keystone Multipurpose loops"
  round 87 hole 63: 1(0,0)
  silkscreen extent -70,-70 70,70, body extent -63,-63 63,62, height 319
Keystone_1902C [mil] "Hex Standoff, 4-40 threaded, nylon"
  round 1 on Mech4: 0(0,0)
  body extent -145,-126 146,126, height 501
"NY PMS 440 0025 PH"#1 [mm] "4-40 nylon screw and mounting hole"
  round 8 hole 3.2: 1(0,0)
  body extent -3.3,-3.3 3.3,3.3, height 2.69
"NY PMS 440 0025 PH"#2 [mm] "4-40 nylon screw and mounting hole"
  round 8 hole 3.2: 1(0,0.254)
  body extent -3.3,-3.3 3.3,3.3, height 2.69
Panasonic_D [mm] "SMD, 2-Leads, Dia 6.3mm"
  rect 3.2x1.6 smd: 1(-2.5,0) 2(2.5,0)
  silkscreen extent -3.4,-3.4 3.4,3.4, body extent -3.4,-3.4 3.4,3.4, height 6.11
Panduit_CXS70-14-C [mil] "Panduit"
  rect 770x500 hole 254 copper offset -74.8,0 paste-250: 1(0,0)
  body extent -960,-250 310,250, height 684
PBC03SAAN [mm] "Sullins 100mil, 1x3, 230 mil above insulator"
  rect 1.65x1.65 hole 1.016: 1(-2.54,0)
  round 1.65 hole 1.016: 2(0,0) 3(2.54,0)
  silkscreen extent -3.81,-1.27 3.81,1.27, body extent -3.81,-1.27 3.81,1.27, height 8.38
RXA0024A-MFG [mm]
  round 0.45 smd paste+0 mask+0: 1(-1.65,2.15) 7(-1.65,-2.15) 12(1.65,-2.15) 20(1.65,2.15)
  rrect40% 0.8x0.25 smd paste+0 mask+0: 2(-1.8,1.375) 3(-1.8,0.75) 4(-1.8,0) 5(-1.8,-0.75) 6(-1.8,-1.375) 13(1.8,-1.5) 14(1.8,-1) 15(1.8,-0.5) 16(1.8,0) 17(1.8,0.5) 18(1.8,1) 19(1.8,1.5)
  rrect40% 0.25x0.75 smd paste+0 mask+0: 8(-0.825,-2.325) 24(-0.825,2.325)
  rrect25% 0.4x0.8 smd paste+0 mask+0: 9(-0.05,-2.3) 23(-0.05,2.3)
  rrect40% 0.25x0.8 smd paste+0 mask+0: 10(0.525,-2.3) 11(1.025,-2.3) 21(1.025,2.3) 22(0.525,2.3)
  rrect7% 1.4x2.4 smd paste-1000 mask+0: 25(0,0)
  Top Layer region: -2.2,2.25 -2.193,2.275 -2.175,2.293 -2.15,2.3 -2.15,2.3 -1.9,2.3 -1.862,2.308 -1.829,2.329 -1.808,2.362 -1.8,2.4 -1.8,2.4 -1.8,2.65 -1.793,2.675 -1.775,2.693 -1.75,2.7 -1.75,2.7 -1.45,2.7 -1.425,2.693 -1.407,2.675 -1.4,2.65 -1.4,2.65 -1.4,1.95 -1.404,1.931 -1.415,1.915 -1.431,1.904 -1.45,1.9 -1.45,1.9 -2.15,1.9 -2.169,1.904 -2.185,1.915 -2.196,1.931 -2.2,1.95 -2.2,1.95
  Top Layer region: 2.2,-2.25 2.196,-2.269 2.185,-2.285 2.169,-2.296 2.15,-2.3 2.15,-2.3 1.9,-2.3 1.862,-2.308 1.829,-2.329 1.808,-2.362 1.8,-2.4 1.8,-2.4 1.8,-2.65 1.793,-2.675 1.775,-2.693 1.75,-2.7 1.75,-2.7 1.45,-2.7 1.425,-2.693 1.407,-2.675 1.4,-2.65 1.4,-2.65 1.4,-1.95 1.404,-1.931 1.415,-1.915 1.431,-1.904 1.45,-1.9 1.45,-1.9 2.15,-1.9 2.169,-1.904 2.185,-1.915 2.196,-1.931 2.2,-1.95 2.2,-1.95
  Top Layer region: 2.2,2.25 2.196,2.269 2.185,2.285 2.169,2.296 2.15,2.3 2.15,2.3 1.9,2.3 1.862,2.308 1.829,2.329 1.808,2.362 1.8,2.4 1.8,2.4 1.8,2.65 1.793,2.675 1.775,2.693 1.75,2.7 1.75,2.7 1.45,2.7 1.425,2.693 1.407,2.675 1.4,2.65 1.4,2.65 1.4,1.95 1.404,1.931 1.415,1.915 1.431,1.904 1.45,1.9 1.45,1.9 2.15,1.9 2.169,1.904 2.185,1.915 2.196,1.931 2.2,1.95 2.2,1.95
  Top Layer region: -2.2,-2.25 -2.196,-2.269 -2.185,-2.285 -2.169,-2.296 -2.15,-2.3 -2.15,-2.3 -1.9,-2.3 -1.862,-2.308 -1.829,-2.329 -1.808,-2.362 -1.8,-2.4 -1.8,-2.4 -1.8,-2.65 -1.793,-2.675 -1.775,-2.693 -1.75,-2.7 -1.75,-2.7 -1.45,-2.7 -1.425,-2.693 -1.407,-2.675 -1.4,-2.65 -1.4,-2.65 -1.4,-1.95 -1.404,-1.931 -1.415,-1.915 -1.431,-1.904 -1.45,-1.9 -1.45,-1.9 -2.15,-1.9 -2.169,-1.904 -2.185,-1.915 -2.196,-1.931 -2.2,-1.95 -2.2,-1.95
  silkscreen extent -2.88,-2.88 2.37,2.88, body extent -2.3,-2.8 2.3,2.8, height 0.25
SNT-100-BK-G [mil] "Samtec STEP model"
  round 1 on Mech3: 0(0,0)
  body extent -100,-50 100,50, height 344
SW_218-2LP [mm] "SMD, 4-Leads, Body 3.71x5.8mm, Pitch 1.27mm"
  rect 1.27x0.76 smd: 1(-3.81,0.635) 2(-3.81,-0.635) 3(3.81,-0.635) 4(3.81,0.635)
  silkscreen extent -2.9,-1.86 2.9,2.09, body extent -4.22,-1.86 4.22,1.85, height 2.62
TSW-102-07-G-S [mm] "Samtec 100mil, 1x2, 230 mil above insulator"
  rrect50% 1.65x1.65 hole 1.016: 1(-1.27,0)
  round 1.65 hole 1.016: 2(1.27,0)
  silkscreen extent -3.17,-1.27 2.54,1.27, body extent -2.54,-1.27 2.54,1.27, height 8.38
WEEE_Minimum [mil] "WEEElie bin"
  silkscreen extent -95,-172 99,104
Wurth_691101710002 [mm] "Terminal Block, 5 mm, 2x1, TH"
  rect 1.8x1.8 hole 1.3: 1(-2.5,0)
  round 1.8 hole 1.3: 2(2.5,0)
  silkscreen extent -5,-4.5 5.6,5, body extent -5.6,-4 5.6,5, height 12.5

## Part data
C1 C2: library part CMP-0011204-2, "CAP, AL, 47 uF, 50 V, +/- 20%, 0.68 ohm, AEC-Q200 Grade 2, SMD", Cap_Case=6.3x5.8mm, Manufacturer=Panasonic, PartNumber=EEEFT1H470AP, Supplier Part Number 1=PCE5023CT-ND, Tolerance_%=20%, Value1="0.68 ohm", Value2=50V, ValueDisplayed=47uF
C3 C4 C27 C28: library part CMP-0085950-1, "CAP, CERM, 10 µF, 50 V,+/- 10%, X7R, AEC-Q200 Grade 1, 1206", Cap_Case=1206, Manufacturer=TDK, PartNumber=CGA5L1X7R1H106K160AC, TempCo=X7R, Tolerance_%=10%, Value2=50V, ValueDisplayed=10µF
C5 C6 C29 C30 C45 C53 C54: library part CMP-0006356-2, "CAP, CERM, 0.1 uF, 50 V, +/- 10%, X7R, AEC-Q200 Grade 1, 0402", Cap_Case=0402, Manufacturer=MuRata, PartNumber=GCM155R71H104KE02D, Supplier Part Number 1=490-10672-1-ND, TempCo=X7R, Tolerance_%=10%, Value1=Unknown, Value2=50V, ValueDisplayed=0.1uF
C7 C17 C25 C31 C39: library part CMP-0007135-4, "CAP, CERM, 0.1 uF, 16 V, +/- 10%, X7R, AEC-Q200 Grade 1, 0603", Cap_Case=0603, Manufacturer=MuRata, Supplier Part Number 1=490-8015-1-ND, TempCo=X7R, Tolerance_%=10%, Value1=Unknown, Value2=16V, ValueDisplayed=0.1uF
C8 C9 C10 C11 C12 C18 C19 C20 C21 C22 C32 C33 C34 C35 C36 C40: library part CMP-0093224-1, "Multi-Layer Ceramic Capacitor 47uF 10VDC X6S 10% 1210 Emboss T/R", Manufacturer=Murata, Mouser Part Number=81-GRT32EC81A476KE3K, Operating Temperature Range="-55°C to +105°C", TempCo=22%, Temperature Characteristic=X6S, Tolerance_%=10%, ValueDisplayed=47uF
C13 C23: library part CMP-0007139-4, "CAP, CERM, 1 uF, 25 V, +/- 10%, X7R, AEC-Q200 Grade 1, 0603", Cap_Case=0603, Manufacturer=MuRata, PartNumber=GCM188R71E105KA64D, Supplier Part Number 1=490-10673-1-ND, TempCo=X7R, Tolerance_%=10%, Value1=Unknown, Value2=25V, ValueDisplayed=1uF
C14 C37: library part CMP-0007010-5, "CAP, CERM, 0.1 uF, 50 V, +/- 10%, X5R, 0603", Cap_Case=0603, Manufacturer=TDK, PartNumber=C1608X5R1H104K080AA, Supplier Part Number 1=445-7456-1-ND, TempCo=X5R, Tolerance_%=10%, Value1="0.0296 ohm", Value2=50V, ValueDisplayed=0.1uF
C15 C38: library part CMP-0007137-5, "CAP, CERM, 1 uF, 16 V, +/- 20%, X7R, AEC-Q200 Grade 1, 0603", Cap_Case=0603, Manufacturer=MuRata, PartNumber=GCM188R71C105MA64D, TempCo=X7R, Tolerance_%=20%, Value1=Unknown, Value2=16V, ValueDisplayed=1uF
C16: library part CMP-0006775-4, "CAP, CERM, 22 pF, 50 V, +/- 5%, C0G/NP0, 0603", Cap_Case=0603, Manufacturer=AVX, PartNumber=06035A220JAT2A, Supplier Part Number 1=478-1167-1-ND, TempCo=C0G/NP0, Tolerance_%=5%, Value1="0.259 ohm", Value2=50V, ValueDisplayed=22pF
C24: library part CMP-0007236-4, "CAP, CERM, 10 pF, 100 V, +/- 5%, C0G/NP0, 0603", Cap_Case=0603, Manufacturer=MuRata, PartNumber=GRM1885C2A100JA01D, Supplier Part Number 1=GRM1885C2A100JA01D-ND, TempCo=C0G/NP0, Tolerance_%=5%, Value1=Unknown, Value2=100V, ValueDisplayed=10pF
C26: library part CMP-0007146-4, "CAP, CERM, 4700 pF, 50 V, +/- 10%, X7R, AEC-Q200 Grade 1, 0603", Cap_Case=0603, Manufacturer=MuRata, Supplier Part Number 1=490-4932-1-ND, TempCo=X7R, Tolerance_%=10%, Value1=Unknown, Value2=50V, ValueDisplayed=4700pF
C46 C49 C50 C51 C52: library part CMP-0007977-2, "CAP, CERM, 2.2 uF, 50 V, +/- 10%, X7R, AEC-Q200 Grade 1, 0805", Cap_Case=0805, Manufacturer=TDK, PartNumber=CGA4J3X7R1H225K125AB, Supplier Part Number 1=445-174216-1-ND, TempCo=X7R, Tolerance_%=10%, Value1="0.003288 ohm", Value2=50V, ValueDisplayed=2.2uF
C47 C48: library part CMP-0006328-2, "CAP, CERM, 0.022 uF, 50 V, +/- 10%, X7R, AEC-Q200 Grade 1, 0402", Cap_Case=0402, Manufacturer=TDK, PartNumber=CGA2B3X7R1H223K050BB, Supplier Part Number 1=445-6895-1-ND, TempCo=X7R, Tolerance_%=10%, Value1="0.141987 ohm", Value2=50V, ValueDisplayed=0.022uF
FB2: library part CMP-0093223-1, "Chip Ferrite Bead Array, 1206, 50O @ 100MHz, 0.0016O, 25%, 12A", Impedance At Frequency="50O @ 100MHz", Manufacturer=Murata, Operating Temperature Range="-55°C to +125?", Test Frequency=100MHz, Tolerance_%=25%
FID1 FID2 FID3: library part CMP-0077181-1, "Fiducial mark.  There is nothing to buy or mount.", Manufacturer=N/A
H1 H2 H3 H4: library part CMP-0003617-1, "Machine Screw, Round, #4-40 x 1/4, Nylon, Philips panhead", Manufacturer="B&F Fastener Supply", Supplier Part Number 1=H542-ND
H5 H6 H7 H8: library part CMP-0003610-1, "Standoff, Hex, 0.5\"L #4-40 Nylon", Manufacturer=Keystone, Supplier Part Number 1=36-1902C-ND
J1 J6: library part CMP-0054828-1, "Terminal Block, 5 mm, 2x1, Tin, TH", Manufacturer="Wurth Elektronik", PartNumber="691 101 710 002", Supplier Part Number 1=732-2026-ND
J2 J3: library part CMP-0055387-2, "Standard Banana Jack, Uninsulated, 15A", Manufacturer="Cinch Connectivity", PartNumber=108-0740-001, Supplier Part Number 1=J147-ND
J4: library part CMP-0075405-3, "Header, 100mil, 2x1, Gold, TH", Color=Black, Current_A=6.3A, Manufacturer=Samtec, PartNumber=TSW-102-07-G-S, Supplier Part Number 1=SAM1029-02-ND, Voltage_V=550V
J5: library part CMP-0002334-1, "Header, 100mil, 3x1, Gold, TH", Manufacturer="Sullins Connector Solutions", PartNumber=PBC03SAAN, Supplier Part Number 1=S1011E-03-ND
L1 L2 L3 L4: library part CMP-0093175-1, "Shielded Power Inductors 3.3uH 20% tol, 6.5mOhm 16.6A", Manufacturer=Coilcraft, Operating Temperature Range=to, Self Resonant Frequency=24MHz, Test Frequency=1MHz, Tolerance_%=20%
L5: library part CMP-0088899-2, "Inductor, Shielded, Composite, 1.0H, 16.9 A, 0.0084 ohm, AEC-Q200 Grade 1", Manufacturer=Coilcraft, Operating Temperature Range="to +165°C", Part Number=XEL5030-102MEB, Self Resonant Frequency=51MHz, Test Frequency=1MHz, Tolerance_%=20%, ValueDisplayed=1uH
Logo1: library part CMP-0074844-1
Logo2: library part CMP-0074837-1, "IEC 61010-1 Hot Surface Warning"
Logo3: library part CMP-0074847-1, "FCC_disclaimer"
Logo4: library part CMP-0074769-1
R1 R15: library part CMP-0081856-1, "RES, 0, 0%, 0.2 W, AEC-Q200 Grade 0, 0402", Manufacturer=Vishay-Dale, PartNumber=CRCW04020000Z0EDHP, Power_W=200mW, Supplier Part Number 1=541-0.0YBTR-ND, Tolerance_%=0%, Value2=0.2W, Value_Code=0
R2 R5 R9 R11: library part CMP-0022200-4, "RES, 200 k, 1%, 0.1 W, AEC-Q200 Grade 0, 0603", Manufacturer=Vishay-Dale, Power_W=100mW, Supplier Part Number 1=541-200KHCT-ND, TempCo="100 ppm/C", Tolerance_%=1%, Value2=0.1W, Value_Code=200k
R3: library part CMP-0025685-3, "RES, 100 k, 0.1%, 0.1 W, AEC-Q200 Grade 1, 0603", Manufacturer=Vishay-Dale, PartNumber=TNPW0603100KBEEA, Power_W=100mW, Supplier Part Number 1=TNP100KAACT-ND, TempCo="25 ppm/C", Tolerance_%=0.1%, Value2=0.1W, Value_Code=100k
R4: library part CMP-0021284-3, "RES, 49.9, 1%, 0.125 W, AEC-Q200 Grade 0, 0805", Manufacturer=Vishay-Dale, PartNumber=CRCW080549R9FKEA, Power_W=125mW, Supplier Part Number 1=541-49.9CCT-ND, TempCo="100 ppm/C", Tolerance_%=1%, Value2=0.125W, Value_Code=49R9, ValueDisplayed=49.9
R6: library part CMP-0024118-3, "RES, 32.0 k, 0.1%, 0.1 W, 0603", Manufacturer="Yageo America", PartNumber=RT0603BRD0732KL, Power_W=100mW, TempCo="25 ppm/C", Tolerance_%=0.1%, Value2=0.1W, Value_Code=32k0, ValueDisplayed=32.0k
R7 R12 R20 R23: library part CMP-0021990-4, "RES, 100 k, 1%, 0.1 W, AEC-Q200 Grade 0, 0603", Manufacturer=Vishay-Dale, Power_W=100mW, Supplier Part Number 1=541-100KHCT-ND, TempCo="100 ppm/C", Tolerance_%=1%, Value2=0.1W, Value_Code=100k
R8: library part CMP-0022735-5, "RES, 100 k, 1%, 0.1 W, 0603", Manufacturer=Yageo, PartNumber=RC0603FR-07100KL, Power_W=100mW, Supplier Part Number 1=311-100KHRCT-ND, TempCo="100 ppm/C", Tolerance_%=1%, Value2=0.1W, Value_Code=100k
R10 R16: library part CMP-0022330-4, "RES, 31.6 k, 1%, 0.1 W, AEC-Q200 Grade 0, 0603", Manufacturer=Vishay-Dale, Power_W=100mW, Supplier Part Number 1=541-31.6KHCT-ND, TempCo="100 ppm/C", Tolerance_%=1%, Value2=0.1W, Value_Code=31k6, ValueDisplayed=31.6k
R13: library part CMP-0022561-4, "RES, 6.49 k, 1%, 0.1 W, AEC-Q200 Grade 0, 0603", Manufacturer=Vishay-Dale, Power_W=100mW, Supplier Part Number 1=541-6.49KHCT-ND, TempCo="100 ppm/C", Tolerance_%=1%, Value2=0.1W, Value_Code=6k49, ValueDisplayed=6.49k
R14: library part CMP-0022585-4, "RES, 73.2 k, 1%, 0.1 W, AEC-Q200 Grade 0, 0603", Manufacturer=Vishay-Dale, Power_W=100mW, Supplier Part Number 1=541-73.2KHCT-ND, TempCo="100 ppm/C", Tolerance_%=1%, Value2=0.1W, Value_Code=73k2, ValueDisplayed=73.2k
R17: library part CMP-0022414-4, "RES, 41.2 k, 1%, 0.1 W, AEC-Q200 Grade 0, 0603", Manufacturer=Vishay-Dale, Power_W=100mW, Supplier Part Number 1=541-41.2KHCT-ND, TempCo="100 ppm/C", Tolerance_%=1%, Value2=0.1W, Value_Code=41k2, ValueDisplayed=41.2k
S1 S2: library part CMP-0002230-1, "Switch, SPST, 2 Pos, 25mA, 24VDC, SMD", CurrentRating_mA=25A, Manufacturer="CTS Electrocomponents", Supplier Part Number 1=CT2182LPST-ND
SH-J1: library part CMP-0003623-3, "Shunt, 100mil, Gold plated, Black", Alternate Manufacturer=3M, Alternate PartNumber=969102-0000-DA, Manufacturer=Samtec, Supplier Part Number 1=SAM8858-ND
T1 T2: library part CMP-0075010-1, "Terminal 70A Lug", Manufacturer=Panduit, PartNumber=CXS70-14-C, Supplier Part Number 1=CXS70-14-C-ND
TP1 TP2 TP4 TP6 TP7 TP8 TP10 TP11 TP12 TP17 TP18: library part CMP-0003968-1, "Test Point, SMT", Manufacturer=Harwin, PartNumber=S2751-46R, Supplier Part Number 1=952-2664-1-ND
TP3: library part CMP-0055147-1, "Test Point, Multipurpose, Red, TH", Color=Red, Manufacturer=Keystone, PartNumber=5010, Supplier Part Number 1=36-5010-ND
TP5: library part CMP-0055150-1, "Test Point, Multipurpose, Orange, TH", Color=Orange, Manufacturer=Keystone, PartNumber=5013, Supplier Part Number 1=36-5013-ND
TP13 TP14 TP15 TP16: library part CMP-0055148-1, "Test Point, Multipurpose, Black, TH", Color=Black, Manufacturer=Keystone, PartNumber=5011, Supplier Part Number 1=36-5011-ND
U1 U2: library part CMP-0091557-1, "LMQ644A2-Q1 3-V to 36-V, 12A, Low Iq dual buck converter", Manufacturer="Texas Instruments", Max Supply Voltage=36V, Min Supply Voltage=3V, Nominal Supply Current=9-25uA, Operating Temperature Range="-40°C to +150°C", Output Voltage=0.8-20V, Switching Frequency=0.1-2.2MHz
ZZ1: library part CMP-0003616-3
ZZ2: library part CMP-0077236-1
ZZ3: library part CMP-0077237-1
ZZ4: library part CMP-0077238-1
ZZ5: library part CMP-0077238-1, "These assemblies must comply with workmanship standards IPC-A-610 Class 2, unless otherwise specified."

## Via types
v1: diameter 20, hole 8, Top Layer to Bottom Layer, tented both sides, 561 vias
v2: diameter 32, hole 16, Top Layer to Bottom Layer, 116 vias
v3: diameter 19.68, hole 7.87, Top Layer to Bottom Layer, 6 vias

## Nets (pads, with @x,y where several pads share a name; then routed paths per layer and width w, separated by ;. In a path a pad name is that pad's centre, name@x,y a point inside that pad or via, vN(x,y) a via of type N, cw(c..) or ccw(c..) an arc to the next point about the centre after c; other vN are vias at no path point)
A: C16.1 J4.2 R3.1 R4.1 | length 561.9
  Top Layer w10: J4.2@990.05,2370 990.05,2319.95 1006.32,2303.68 1006.32,2017.25 1017.14,2006.42 R3.1@1048.33,2006.42
  Bottom Layer w10: v1(1019.45,2006.24) 1019.64,2006.42 C16.1@1048.33,2006.42
  Bottom Layer w15: J4.2@990.05,2370 990.05,2319.95 1006.32,2303.68 R4.1@1006.32,2249.81
BIAS/VOSNS1_P: C14.2 R1.1 U1.13 | length 241.5
  Top Layer w10: C14.2@1100.65,2043.88 1128.96,2043.88 1138.25,2034.58 1138.25,1933.88 1153.45,1918.68 U1.13@1181.56,1918.68 ; C14.2@1103.45,2055 1104.69,2056.23 R1.1@1104.68,2104.26
BIAS/VOSNS1_S: C37.2 R15.2 U2.13 | length 138.2
  Top Layer w10: R15.2@1105.29,1203.88 1105.29,1158.95 C37.2@1104.31,1157.97 1139.75,1122.54 U2.13@1181.56,1122.54
BOOT1: C7.1 U1.6 | length 107.8
  Top Layer w10: U1.6@1323.29,1913.76 1354.91,1913.76 1361.8,1920.65 1361.8,1942.19 1370.22,1950.61 C7.1@1403.18,1950.61
BOOT2: C17.2 U1.2 | length 109.2
  Top Layer w10: U1.2@1323.29,1805.49 1354.25,1805.49 1361.8,1797.94 1361.8,1774.29 1367.99,1768.09 C17.2@1403.18,1768.09
BOOT3: C31.2 U2.6 | length 101.1
  Top Layer w10: U2.6@1323.29,1117.62 1346.14,1117.62 1356.8,1128.27 1356.8,1140.65 1367.59,1151.44 C31.2@1403.18,1151.44
BOOT4: C39.1 U2.2 | length 107.7
  Top Layer w10: U2.2@1323.29,1009.35 1343.51,1009.35 1355.03,997.83 1355.03,977.24 1360.95,971.32 C39.1@1403.18,971.32
CNFG_P: R14.2 U1.21 | length 219
  Top Layer w10: R14.2@1097.85,1617.39 1131.99,1617.39 1149.83,1635.23 1149.83,1675.86 1196.04,1722.07 1196.04,1737.66 1212.07,1753.69 U1.21@1212.07,1769.08
CNFG_S: R17.2 U2.21 | length 149.1
  Top Layer w10: R17.2@1108.37,891.85 1151.16,891.85 1212.07,952.76 U2.21@1212.07,972.93
COMP: C24.2 R13.2 U1.19 U2.19 | length 1175.9
  Top Layer w10: R13.2@1049.88,1726.13 1052.07,1728.32 v1(1075,1728.32) C24.2@1101.8,1728.32 1121.66,1728.32 1138.25,1744.92 1138.25,1777.08 1161.75,1800.57 U1.19@1181.56,1800.57 ; v1(1111.01,959.59) 1114.41,959.59 1159.25,1004.43 U2.19@1181.56,1004.43
  Signal Layer 1 w10: v1(1075,1728.32) 1030.35,1728.32 1030.35,1726.82 1006.32,1702.79 1006.32,998.24 1044.97,959.59 v1(1111.01,959.59)
EN1: R7.2 S1.4 U1.12 | length 957.5
  Top Layer w10: v1(1161.75,1980) 1161.75,1970 U1.12@1187.47,1944.27
  Top Layer w15: S1.4@901.68,2564.19 v1(956.51,2564.19)
  Signal Layer3 w15: v1(956.51,2564.19) 1111.74,2564.19 1220.93,2455 1220.27,2454.34 v1(1220.27,2305)
  Bottom Layer w10: v1(1161.75,1980) 1143.25,1998.49 1143.25,2190.57 1159.45,2206.76 1210,2206.76 1222.9,2219.66 R7.2@1222.9,2247.9 R7.2@1220.27,2250.53
  Bottom Layer w20: R7.2@1220.27,2250.53 v1(1220.27,2305)
EN2: R12.2 S1.3 U1.20 | length 2276
  Top Layer w10: v1(586.9,2646.68) 619.36,2679.14 872.26,2679.14 901.68,2649.72 S1.3@901.68,2614.19 ; v1(1154.07,1718.08) 1154.07,1731.74 1187.47,1765.14 U1.20@1187.47,1774.98
  Signal Layer 1 w10: v1(586.9,2646.68) 586.9,2219.49 738,2068.39 738,1635 v1(830.32,1542.68) ; v1(1154.07,1718.08) 1154.07,1573.93 1189,1539 v1(1190,1539)
  Bottom Layer w10: v1(830.32,1542.68) 897.5,1475.5 1113.38,1475.5 1150.62,1512.74 R12.2@1150.62,1539.5
  Bottom Layer w25: R12.2@1150.62,1539.5 1151.12,1539 v1(1190,1539)
EN3: R20.2 S2.4 U2.12 | length 1857.9
  Top Layer w15: v1(1143.97,1155.02) 1150.86,1148.13 U2.12@1187.47,1148.13
  Top Layer w25: v1(829.59,335) S2.4@901.68,335
  Signal Layer 1 w10: v1(1143.97,1155.02) 1144.16,1155.21 1144.16,1370 1155.16,1381 v1(1185.85,1381)
  Signal Layer 1 w15: v1(829.59,1424) 830,643.58 v1@830,335.41
  Bottom Layer w10: v1(829.59,1424) 1133.58,1424 1150.07,1407.51 R20.2@1150.07,1381
  Bottom Layer w25: R20.2@1150.07,1381 v1(1185.85,1381)
EN4: R23.2 S2.3 U2.20 | length 843.4
  Top Layer w15: v1(1157.15,948.52) 1157.15,952.45 1177.62,972.93
  Top Layer w25: v1(900,435.85) 900,386.68 S2.3@901.68,385
  Signal Layer3 w15: v1(900,435.85) 900,464.71 929.55,494.26 1080,494.26 1183.14,597.4 v1(1183.14,672.57)
  Bottom Layer w15: v1(1157.15,948.52) 1121.33,912.7 1121.33,804.96 1183.68,742.6 R23.2@1183.68,716
  Bottom Layer w20: v1(1183.14,672.57) 1183.14,715.45 R23.2@1183.68,716
FB1: C16.2 R3.2 R6.2 U1.14 | length 188.2
  Top Layer w10: R3.2@1103.45,2006.42 v1(1103.45,1976.24) 1103.45,1946.05 1150.51,1899 U1.14@1181.56,1899
  Bottom Layer w10: v1(1103.45,1976.24) C16.2@1103.45,2006.42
